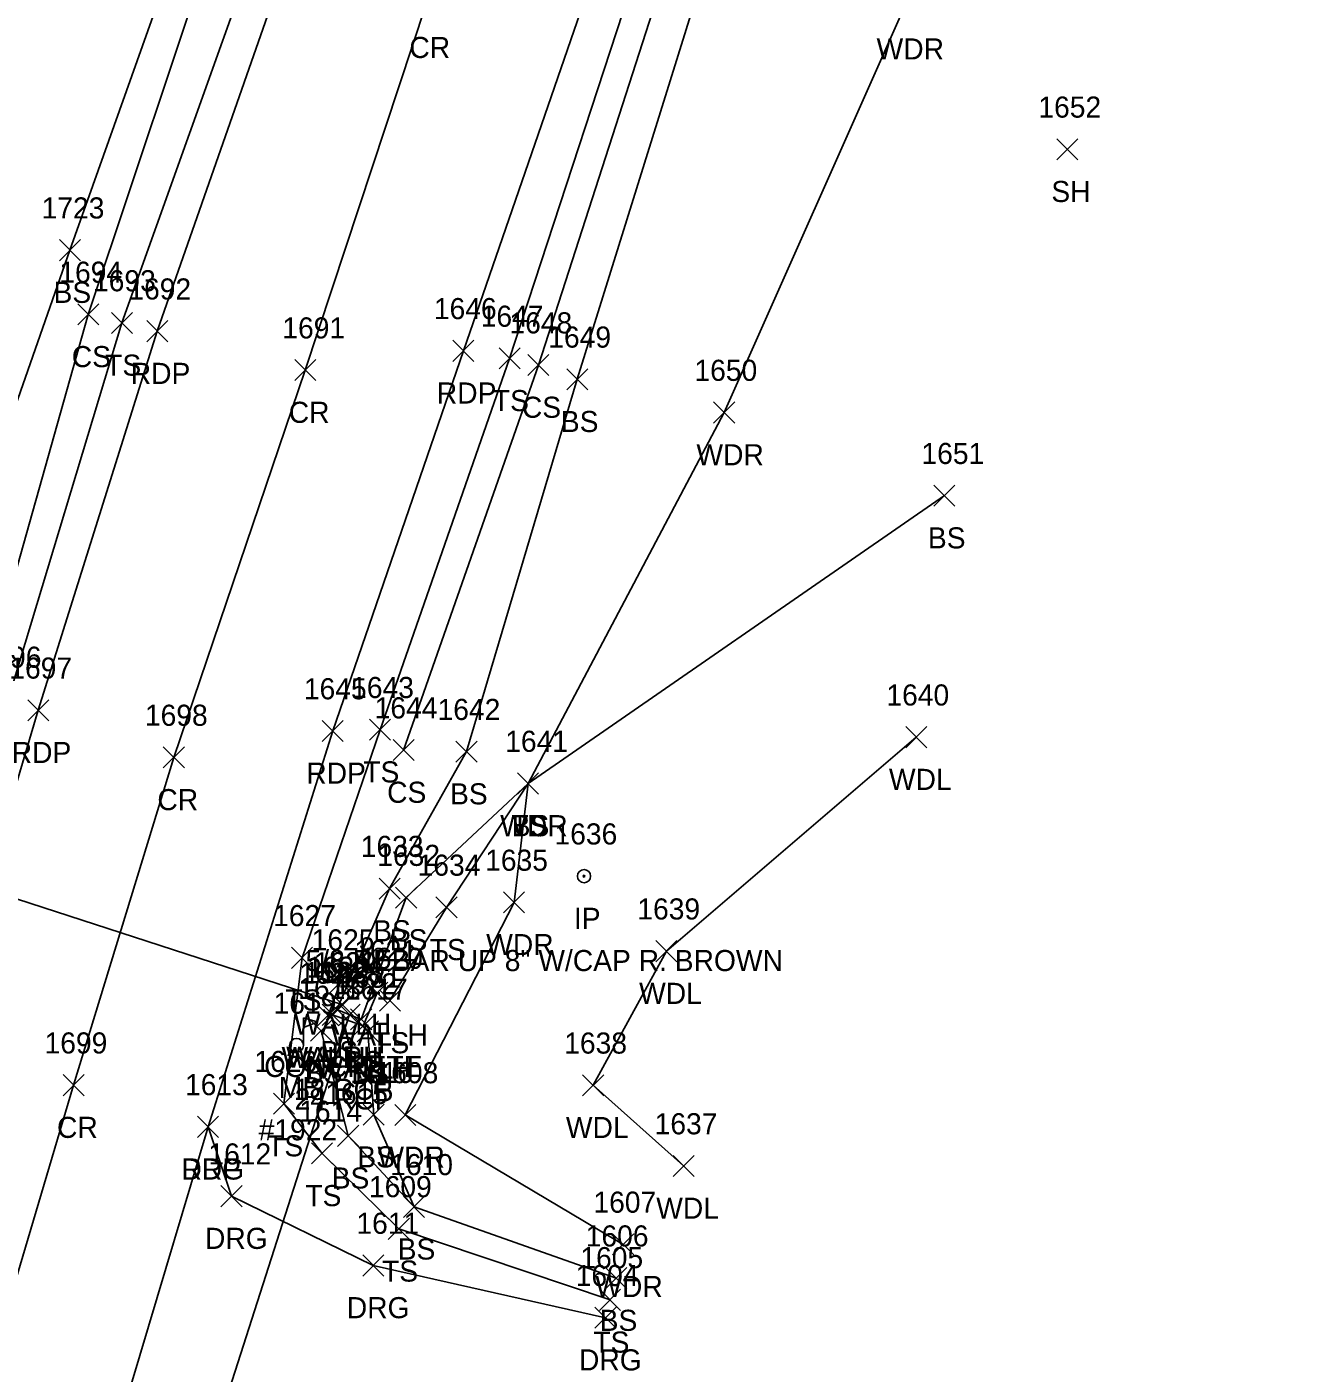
# Model space of a CAD drawing. Extents: x 1654425 to 1656893, y 667839 to 678429.
# Drawn here: x 1654668.3 to 1654790.4, y 668618 to 668745.6 of the extents above; entities that cross this region are included whole.
import ezdxf

# ---------------------------------------------------------------- set-up
doc = ezdxf.new("R2010")
doc.units = 0
for name, color, linetype in [('D_A', 7, 'Continuous'), ('D_C', 7, 'Continuous'), ('D_I', 7, 'Continuous'), ('D_TIC', 7, 'Continuous'), ('DCP', 7, 'Continuous'), ('DHW', 7, 'Continuous'), ('L_A', 7, 'Continuous'), ('L_C', 7, 'Continuous'), ('L_I', 7, 'Continuous'), ('L_TIC', 7, 'Continuous'), ('LAWA', 7, 'Continuous'), ('LELB', 7, 'Continuous'), ('LMB', 7, 'Continuous'), ('M_A', 7, 'Continuous'), ('M_C', 7, 'Continuous'), ('M_I', 7, 'Continuous'), ('MPIR', 7, 'Continuous'), ('P_A', 7, 'Continuous'), ('P_I', 7, 'Continuous'), ('P_TIC', 7, 'Continuous'), ('PET', 7, 'Continuous'), ('PRC', 7, 'Continuous'), ('R_A', 7, 'Continuous'), ('R_I', 7, 'Continuous'), ('R_TIC', 7, 'Continuous'), ('RDG', 7, 'Continuous')]:
    doc.layers.add(name, color=color, linetype=linetype)

msp = doc.modelspace()

# ---------------------------------------------------------------- linework, layer by layer
at = {"layer": 'D_TIC'}
for points in [[(1654697.01, 668654.08), (1654699.01, 668656.08)], [(1654699.01, 668654.08), (1654697.01, 668656.08)], [(1654697.21, 668651.91), (1654699.21, 668653.91)], [(1654699.21, 668651.91), (1654697.21, 668653.91)], [(1654700.48, 668653.06), (1654702.48, 668655.06)], [(1654702.48, 668653.06), (1654700.48, 668655.06)], [(1654695.83, 668650.92), (1654697.83, 668652.92)], [(1654697.83, 668650.92), (1654695.83, 668652.92)], [(1654696.26, 668650.97), (1654698.26, 668652.97)], [(1654698.26, 668650.97), (1654696.26, 668652.97)], [(1654697.87, 668651), (1654699.87, 668653)], [(1654699.87, 668651), (1654697.87, 668653)], [(1654699.15, 668649.92), (1654701.15, 668651.92)], [(1654701.15, 668649.92), (1654699.15, 668651.92)]]:
    msp.add_lwpolyline(points, dxfattribs=at)
at = {"layer": 'DCP'}
for points in [[(1654698.21, 668652.91), (1654651.24, 668668.18)], [(1654670.02, 668562.02), (1654698.87, 668652)]]:
    msp.add_lwpolyline(points, dxfattribs=at)
at = {"layer": 'DHW'}
for points in [[(1654696.83, 668651.92), (1654698.01, 668655.08)], [(1654701.48, 668654.06), (1654700.15, 668650.92), (1654697.26, 668651.97)]]:
    msp.add_lwpolyline(points, dxfattribs=at)
at = {"layer": 'L_TIC'}
for points in [[(1654765.87, 668733.01), (1654767.87, 668735.01)], [(1654767.87, 668733.01), (1654765.87, 668735.01)], [(1654671.37, 668723.45), (1654673.37, 668725.45)], [(1654673.37, 668723.45), (1654671.37, 668725.45)], [(1654673.1, 668717.36), (1654675.1, 668719.36)], [(1654675.1, 668717.36), (1654673.1, 668719.36)], [(1654676.29, 668716.55), (1654678.29, 668718.55)], [(1654678.29, 668716.55), (1654676.29, 668718.55)], [(1654713.03, 668713.19), (1654715.03, 668715.19)], [(1654715.03, 668713.19), (1654713.03, 668715.19)], [(1654715.75, 668712.56), (1654717.75, 668714.56)], [(1654717.75, 668712.56), (1654715.75, 668714.56)], [(1654719.44, 668711.21), (1654721.44, 668713.21)], [(1654721.44, 668711.21), (1654719.44, 668713.21)], [(1654733.36, 668708.06), (1654735.36, 668710.06)], [(1654735.36, 668708.06), (1654733.36, 668710.06)], [(1654754.22, 668700.18), (1654756.22, 668702.18)], [(1654756.22, 668700.18), (1654754.22, 668702.18)], [(1654700.75, 668678), (1654702.75, 668680)], [(1654702.75, 668678), (1654700.75, 668680)], [(1654751.56, 668677.29), (1654753.56, 668679.29)], [(1654753.56, 668677.29), (1654751.56, 668679.29)], [(1654702.98, 668676.07), (1654704.98, 668678.07)], [(1654704.98, 668676.07), (1654702.98, 668678.07)], [(1654708.94, 668675.92), (1654710.94, 668677.92)], [(1654710.94, 668675.92), (1654708.94, 668677.92)], [(1654714.78, 668672.9), (1654716.78, 668674.9)], [(1654716.78, 668672.9), (1654714.78, 668674.9)], [(1654714.78, 668672.9), (1654716.78, 668674.9)], [(1654716.78, 668672.9), (1654714.78, 668674.9)], [(1654714.78, 668672.9), (1654716.78, 668674.9)], [(1654716.78, 668672.9), (1654714.78, 668674.9)], [(1654701.66, 668662.94), (1654703.66, 668664.94)], [(1654703.66, 668662.94), (1654701.66, 668664.94)], [(1654703.23, 668662.09), (1654705.23, 668664.09)], [(1654705.23, 668662.09), (1654703.23, 668664.09)], [(1654707.05, 668661.16), (1654709.05, 668663.16)], [(1654709.05, 668661.16), (1654707.05, 668663.16)], [(1654713.45, 668661.63), (1654715.45, 668663.63)], [(1654715.45, 668661.63), (1654713.45, 668663.63)], [(1654727.88, 668657.01), (1654729.88, 668659.01)], [(1654729.88, 668657.01), (1654727.88, 668659.01)], [(1654693.36, 668656.38), (1654695.36, 668658.38)], [(1654695.36, 668656.38), (1654693.36, 668658.38)], [(1654701.69, 668652.33), (1654703.69, 668654.33)], [(1654703.69, 668652.33), (1654701.69, 668654.33)], [(1654696.66, 668651.49), (1654698.66, 668653.49)], [(1654698.66, 668651.49), (1654696.66, 668653.49)], [(1654696.66, 668651.49), (1654698.66, 668653.49)], [(1654698.66, 668651.49), (1654696.66, 668653.49)], [(1654695.17, 668649.47), (1654697.17, 668651.47)], [(1654697.17, 668649.47), (1654695.17, 668651.47)], [(1654698.96, 668650.54), (1654700.96, 668652.54)], [(1654700.96, 668650.54), (1654698.96, 668652.54)], [(1654699.59, 668649.41), (1654701.59, 668651.41)], [(1654701.59, 668649.41), (1654699.59, 668651.41)], [(1654720.94, 668644.3), (1654722.94, 668646.3)], [(1654722.94, 668644.3), (1654720.94, 668646.3)], [(1654691.64, 668642.56), (1654693.64, 668644.56)], [(1654693.64, 668642.56), (1654691.64, 668644.56)], [(1654700.15, 668641.51), (1654702.15, 668643.51)], [(1654702.15, 668641.51), (1654700.15, 668643.51)], [(1654703.14, 668641.49), (1654705.14, 668643.49)], [(1654705.14, 668641.49), (1654703.14, 668643.49)], [(1654697.73, 668639.51), (1654699.73, 668641.51)], [(1654699.73, 668639.51), (1654697.73, 668641.51)], [(1654695.26, 668637.84), (1654697.26, 668639.84)], [(1654697.26, 668637.84), (1654695.26, 668639.84)], [(1654729.51, 668636.65), (1654731.51, 668638.65)], [(1654731.51, 668636.65), (1654729.51, 668638.65)], [(1654703.97, 668632.78), (1654705.97, 668634.78)], [(1654705.97, 668632.78), (1654703.97, 668634.78)], [(1654703.97, 668632.78), (1654705.97, 668634.78)], [(1654705.97, 668632.78), (1654703.97, 668634.78)], [(1654702.53, 668630.69), (1654704.53, 668632.69)], [(1654704.53, 668630.69), (1654702.53, 668632.69)], [(1654723.79, 668629.22), (1654725.79, 668631.22)], [(1654725.79, 668629.22), (1654723.79, 668631.22)], [(1654723.12, 668626.02), (1654725.12, 668628.02)], [(1654725.12, 668626.02), (1654723.12, 668628.02)], [(1654722.55, 668623.96), (1654724.55, 668625.96)], [(1654724.55, 668623.96), (1654722.55, 668625.96)]]:
    msp.add_lwpolyline(points, dxfattribs=at)
at = {"layer": 'LAWA'}
for points in [[(1654724.79, 668630.22), (1654704.14, 668642.49), (1654714.45, 668662.63), (1654715.78, 668673.9), (1654734.36, 668709.06), (1654751.44, 668747.52), (1654760.59, 668785.86), (1654768.71, 668809.1), (1654790.44, 668855.54)], [(1654730.51, 668637.65), (1654721.94, 668645.3), (1654728.88, 668658.01), (1654752.56, 668678.29)]]:
    msp.add_lwpolyline(points, dxfattribs=at)
at = {"layer": 'LELB'}
for points in [[(1654581.88, 668581.9), (1654606.98, 668576.45), (1654627.8, 668578.91), (1654641.17, 668616.39), (1654649.87, 668649.23), (1654649.52, 668665.58), (1654651.97, 668671.89), (1654662.51, 668696.29), (1654672.37, 668724.45), (1654685.62, 668761.8), (1654697.84, 668800.3), (1654711.19, 668841.94), (1654722.77, 668879.71)], [(1654727.34, 668878.17), (1654715.11, 668842.6), (1654700.71, 668798.51), (1654686.43, 668755.34), (1654674.1, 668718.36), (1654664.15, 668683.1), (1654653.32, 668648.82)], [(1654730.44, 668877.26), (1654718.47, 668840.65), (1654704.15, 668797.51), (1654690.11, 668753.49), (1654677.29, 668717.55), (1654666.51, 668681.87), (1654655.17, 668648.77)], [(1654723.55, 668624.96), (1654703.53, 668631.69), (1654696.26, 668638.84), (1654692.64, 668643.56), (1654694.36, 668657.38), (1654701.75, 668679), (1654714.03, 668714.19), (1654727.77, 668756.18), (1654739.32, 668794.57), (1654748.89, 668818.21), (1654763.68, 668865.47)], [(1654697.66, 668652.49), (1654702.66, 668663.94), (1654709.94, 668676.92), (1654720.44, 668712.21), (1654733.96, 668755.64), (1654746.96, 668793.09), (1654755.27, 668814.99), (1654770.45, 668863.44)], [(1654703.98, 668677.07), (1654716.75, 668713.56), (1654730.13, 668754.99), (1654741.78, 668794.23), (1654748.89, 668818.21)], [(1654697.66, 668652.49), (1654699.96, 668651.54), (1654704.23, 668663.09), (1654715.78, 668673.9), (1654755.22, 668701.18)], [(1654702.69, 668653.33), (1654708.05, 668662.16), (1654715.78, 668673.9)], [(1654724.12, 668627.02), (1654704.97, 668633.78), (1654698.73, 668640.51), (1654696.17, 668650.47)], [(1654704.97, 668633.78), (1654701.15, 668642.51), (1654700.59, 668650.41)]]:
    msp.add_lwpolyline(points, dxfattribs=at)
at = {"layer": 'LMB'}
for p, q in [((1654694.49, 668651.68), (1654695.78, 668651.3)), ((1654694.5, 668649.09), (1654694.5, 668651.69)), ((1654694.5, 668650.78), (1654695.78, 668651.29)), ((1654693.84, 668649.08), (1654693.84, 668649.08))]:
    msp.add_line(p, q, dxfattribs=at)
msp.add_circle((1654693.84, 668649.08), 0.656, dxfattribs=at)
at = {"layer": 'MPIR'}
for radius in [0.625, 0.0833]:
    msp.add_circle((1654721.08, 668665.12), radius, dxfattribs=at)
at = {"layer": 'P_TIC'}
for points in [[(1654679.64, 668715.77), (1654681.64, 668717.77)], [(1654681.64, 668715.77), (1654679.64, 668717.77)], [(1654708.65, 668713.91), (1654710.65, 668715.91)], [(1654710.65, 668713.91), (1654708.65, 668715.91)], [(1654693.67, 668712.08), (1654695.67, 668714.08)], [(1654695.67, 668712.08), (1654693.67, 668714.08)], [(1654668.36, 668679.84), (1654670.36, 668681.84)], [(1654670.36, 668679.84), (1654668.36, 668681.84)], [(1654696.27, 668677.88), (1654698.27, 668679.88)], [(1654698.27, 668677.88), (1654696.27, 668679.88)], [(1654681.21, 668675.37), (1654683.21, 668677.37)], [(1654683.21, 668675.37), (1654681.21, 668677.37)], [(1654671.71, 668644.31), (1654673.71, 668646.31)], [(1654673.71, 668644.31), (1654671.71, 668646.31)], [(1654671.71, 668644.31), (1654673.71, 668646.31)], [(1654673.71, 668644.31), (1654671.71, 668646.31)], [(1654684.45, 668640.36), (1654686.45, 668642.36)], [(1654686.45, 668640.36), (1654684.45, 668642.36)]]:
    msp.add_lwpolyline(points, dxfattribs=at)
at = {"layer": 'PET'}
for points in [[(1654734.29, 668876.05), (1654722, 668839.15), (1654707.71, 668796.62), (1654693.12, 668752.48), (1654680.64, 668716.77), (1654669.36, 668680.84), (1654659.58, 668647.93)], [(1654621.12, 668380.08), (1654629.57, 668415.34), (1654638.69, 668455.31), (1654647.1, 668497.17), (1654655.08, 668532.73), (1654664.14, 668568.47), (1654670.36, 668590.98), (1654672.51, 668598), (1654685.45, 668641.36), (1654697.27, 668678.88), (1654709.65, 668714.91), (1654724.45, 668757.78), (1654737.22, 668795.28), (1654745.33, 668819.59), (1654761.32, 668866.34)]]:
    msp.add_lwpolyline(points, dxfattribs=at)
at = {"layer": 'PRC'}
for points in [[(1654747.78, 668871.19), (1654735.21, 668834.5), (1654721.54, 668793.61), (1654706.09, 668747.66), (1654694.67, 668713.08), (1654682.21, 668676.37), (1654672.71, 668645.31)], [(1654605.24, 668384.01), (1654612.68, 668416.68), (1654623.19, 668461.23), (1654632.58, 668500.46), (1654641.79, 668536.76), (1654650.75, 668570.78), (1654657.62, 668594.43), (1654672.71, 668645.31)]]:
    msp.add_lwpolyline(points, dxfattribs=at)
at = {"layer": 'R_TIC'}
for points in [[(1654684.45, 668640.36), (1654686.45, 668642.36)], [(1654686.45, 668640.36), (1654684.45, 668642.36)], [(1654686.67, 668633.79), (1654688.67, 668635.79)], [(1654688.67, 668633.79), (1654686.67, 668635.79)], [(1654700.11, 668627.22), (1654702.11, 668629.22)], [(1654702.11, 668627.22), (1654700.11, 668629.22)], [(1654722.11, 668622.27), (1654724.11, 668624.27)], [(1654724.11, 668622.27), (1654722.11, 668624.27)]]:
    msp.add_lwpolyline(points, dxfattribs=at)
at = {"layer": 'RDG'}
msp.add_lwpolyline([(1654723.11, 668623.27), (1654701.11, 668628.22), (1654687.67, 668634.79), (1654685.45, 668641.36)], dxfattribs=at)

# ---------------------------------------------------------------- texts
at = {"layer": 'D_A'}
for s, p in [('WALLH', (1654693.6, 668650.08)), ('WALLH', (1654697.07, 668649.06)), ('WALLH', (1654692.42, 668646.92)), ('WALLH', (1654692.85, 668646.97)), ('P', (1654697.59, 668647.91)), ('P', (1654698.25, 668647)), ('WALLH', (1654695.74, 668645.92))]:
    msp.add_text(s, height=2, dxfattribs=at).set_placement(p)
at = {"layer": 'D_C'}
for s, p in [('CONCRETE', (1654690.77, 668646.08)), ('18 RCP', (1654693.58, 668643.91)), ('24 RCP', (1654693.66, 668643))]:
    msp.add_text(s, height=2, dxfattribs=at).set_placement(p)
at = {"layer": 'D_I'}
for s, p in [('1625', (1654695.27, 668658.08)), ('1621', (1654699.31, 668657.06)), ('1629', (1654695.47, 668655.91)), ('1624', (1654694.09, 668654.92)), ('1623', (1654694.52, 668654.97)), ('1628', (1654696.13, 668655)), ('1622', (1654697.41, 668653.92))]:
    msp.add_text(s, height=2, dxfattribs=at).set_placement(p)
at = {"layer": 'L_A'}
for s, p in [('WDR', (1654748.8, 668742.52)), ('SH', (1654765.36, 668729.01)), ('BS', (1654670.81, 668719.45)), ('CS', (1654672.54, 668713.36)), ('TS', (1654675.7, 668712.55)), ('TS', (1654712.44, 668709.19)), ('CS', (1654715.19, 668708.56)), ('BS', (1654718.88, 668707.21)), ('WDR', (1654731.73, 668704.06)), ('BS', (1654753.66, 668696.18)), ('TS', (1654700.16, 668674)), ('WDL', (1654749.97, 668673.29)), ('CS', (1654702.42, 668672.07)), ('BS', (1654708.38, 668671.92)), ('WDR', (1654713.14, 668668.9)), ('TS', (1654714.19, 668668.9)), ('BS', (1654714.22, 668668.9)), ('BS', (1654701.1, 668658.94)), ('BS', (1654702.67, 668658.09)), ('TS', (1654706.46, 668657.16)), ('WDR', (1654711.81, 668657.63)), ('TS', (1654692.77, 668652.38)), ('WDL', (1654726.3, 668653.01)), ('TS', (1654701.1, 668648.33)), ('BS', (1654696.1, 668647.49)), ('BS', (1654696.1, 668647.49)), ('BS', (1654698.4, 668646.54)), ('BS', (1654694.61, 668645.47)), ('BS', (1654699.03, 668645.41)), ('MB', (1654692.15, 668644.08)), ('WDL', (1654719.36, 668640.3)), ('TS', (1654691.05, 668638.56)), ('BS', (1654699.59, 668637.51)), ('WDR', (1654701.5, 668637.49)), ('BS', (1654697.17, 668635.51)), ('TS', (1654694.67, 668633.84)), ('WDL', (1654727.92, 668632.65)), ('BS', (1654703.42, 668628.78)), ('BS', (1654703.42, 668628.78)), ('TS', (1654701.94, 668626.69)), ('WDR', (1654722.15, 668625.22)), ('BS', (1654722.56, 668622.02)), ('TS', (1654721.96, 668619.96))]:
    msp.add_text(s, height=2, dxfattribs=at).set_placement(p)
at = {"layer": 'L_C'}
msp.add_text('#1922', height=2, dxfattribs=at).set_placement((1654690.25, 668640.08))
at = {"layer": 'L_I'}
for s, p in [('1652', (1654764.13, 668737.01)), ('1723', (1654669.68, 668727.45)), ('1694', (1654671.36, 668721.36)), ('1693', (1654674.55, 668720.55)), ('1647', (1654711.29, 668717.19)), ('1648', (1654714.01, 668716.56)), ('1649', (1654717.69, 668715.21)), ('1650', (1654731.54, 668712.06)), ('1651', (1654753.05, 668704.18)), ('1696', (1654663.72, 668684.87)), ('1643', (1654699.01, 668682)), ('1640', (1654749.73, 668681.29)), ('1644', (1654701.24, 668680.07)), ('1642', (1654707.2, 668679.92)), ('1641', (1654713.61, 668676.9)), ('1641', (1654713.61, 668676.9)), ('1641', (1654713.61, 668676.9)), ('1633', (1654699.92, 668666.94)), ('1632', (1654701.49, 668666.09)), ('1634', (1654705.31, 668665.16)), ('1635', (1654711.71, 668665.63)), ('1639', (1654726.13, 668661.01)), ('1627', (1654691.62, 668660.38)), ('1620', (1654699.86, 668656.33)), ('1630', (1654694.83, 668655.49)), ('1630', (1654694.83, 668655.49)), ('1631', (1654697.79, 668654.54)), ('1618', (1654694, 668653.47)), ('1617', (1654698.42, 668653.41)), ('1619', (1654691.66, 668652.08)), ('1638', (1654719.2, 668648.3)), ('1626', (1654689.84, 668646.56)), ('1616', (1654698.92, 668645.51)), ('1608', (1654701.32, 668645.49)), ('1615', (1654696.55, 668643.51)), ('1614', (1654694.09, 668641.84)), ('1637', (1654727.77, 668640.65)), ('1610', (1654702.71, 668636.78)), ('1610', (1654702.71, 668636.78)), ('1609', (1654700.7, 668634.69)), ('1607', (1654721.97, 668633.22)), ('1606', (1654721.24, 668630.02)), ('1605', (1654720.73, 668627.96))]:
    msp.add_text(s, height=2, dxfattribs=at).set_placement(p)
at = {"layer": 'M_A'}
msp.add_text('IP', height=2, dxfattribs=at).set_placement((1654720.12, 668660.12))
at = {"layer": 'M_C'}
msp.add_text('5/8 REBAR UP 8" W/CAP R. BROWN', height=2, dxfattribs=at).set_placement((1654694.69, 668656.12))
at = {"layer": 'M_I'}
msp.add_text('1636', height=2, dxfattribs=at).set_placement((1654718.28, 668668.12))
at = {"layer": 'P_A'}
for s, p in [('CR', (1654704.53, 668742.66)), ('RDP', (1654678.13, 668711.77)), ('RDP', (1654707.13, 668709.91)), ('CR', (1654693.1, 668708.08)), ('RDP', (1654666.85, 668675.84)), ('RDP', (1654694.76, 668673.88)), ('CR', (1654680.65, 668671.37)), ('CR', (1654671.14, 668640.31)), ('CR', (1654671.14, 668640.31)), ('RDP', (1654682.93, 668636.36))]:
    msp.add_text(s, height=2, dxfattribs=at).set_placement(p)
at = {"layer": 'P_I'}
for s, p in [('1692', (1654677.9, 668719.77)), ('1646', (1654706.85, 668717.91)), ('1691', (1654692.49, 668716.08)), ('1697', (1654666.62, 668683.84)), ('1645', (1654694.53, 668681.88)), ('1698', (1654679.47, 668679.37)), ('1699', (1654669.96, 668648.31)), ('1699', (1654669.96, 668648.31)), ('1613', (1654683.27, 668644.36))]:
    msp.add_text(s, height=2, dxfattribs=at).set_placement(p)
at = {"layer": 'R_A'}
for p in [(1654682.93, 668636.36), (1654685.16, 668629.79), (1654698.6, 668623.22), (1654720.6, 668618.27)]:
    msp.add_text('DRG', height=2, dxfattribs=at).set_placement(p)
at = {"layer": 'R_I'}
for s, p in [('1613', (1654683.27, 668644.36)), ('1612', (1654685.49, 668637.79)), ('1611', (1654699.51, 668631.22)), ('1604', (1654720.29, 668626.27))]:
    msp.add_text(s, height=2, dxfattribs=at).set_placement(p)

doc.saveas('drawing.dxf')
